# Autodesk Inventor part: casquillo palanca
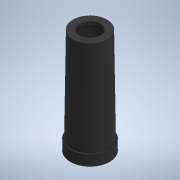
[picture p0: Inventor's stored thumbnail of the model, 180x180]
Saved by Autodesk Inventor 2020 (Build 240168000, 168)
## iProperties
Created: 2022-02
Part Number: casquillo palanca
Material: Genérico
Document SubType Name: Modeling
Designer: Eresthor
Density: 1 g/cm^3
Appearance: Goma - Negro
Author: Eresthor
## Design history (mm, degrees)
sketch "Boceto1"
  geometry: L1 (0, 0)-(0, 40); L2 (-4, 40)-(-6.5, 40); L3 (-6.5, 0)-(-7.5, 0); L4 (-7.5, 0)-(-7.5, 4); L5 (-7.5, 4)-(-7, 4); L6 (-7, 4)-(-6.5, 40); L7 (-4, 39)-(-5.514, 39); L8 (-5.514, 39)-(-6.014, 3); L9 (-6.014, 3)-(-6.5, 3); L10 (-6.5, 0)-(-6.5, 3); L11 (-4, 40)-(-4, 39); 2 further points
  constraints: 22 end point, 5 perpendicular, 1 horizontal, 1 vertical
revolve "Revolución1" sketch "Boceto1" stored, may be unused: angle "d8" = 90 deg
node "Sólido1"
